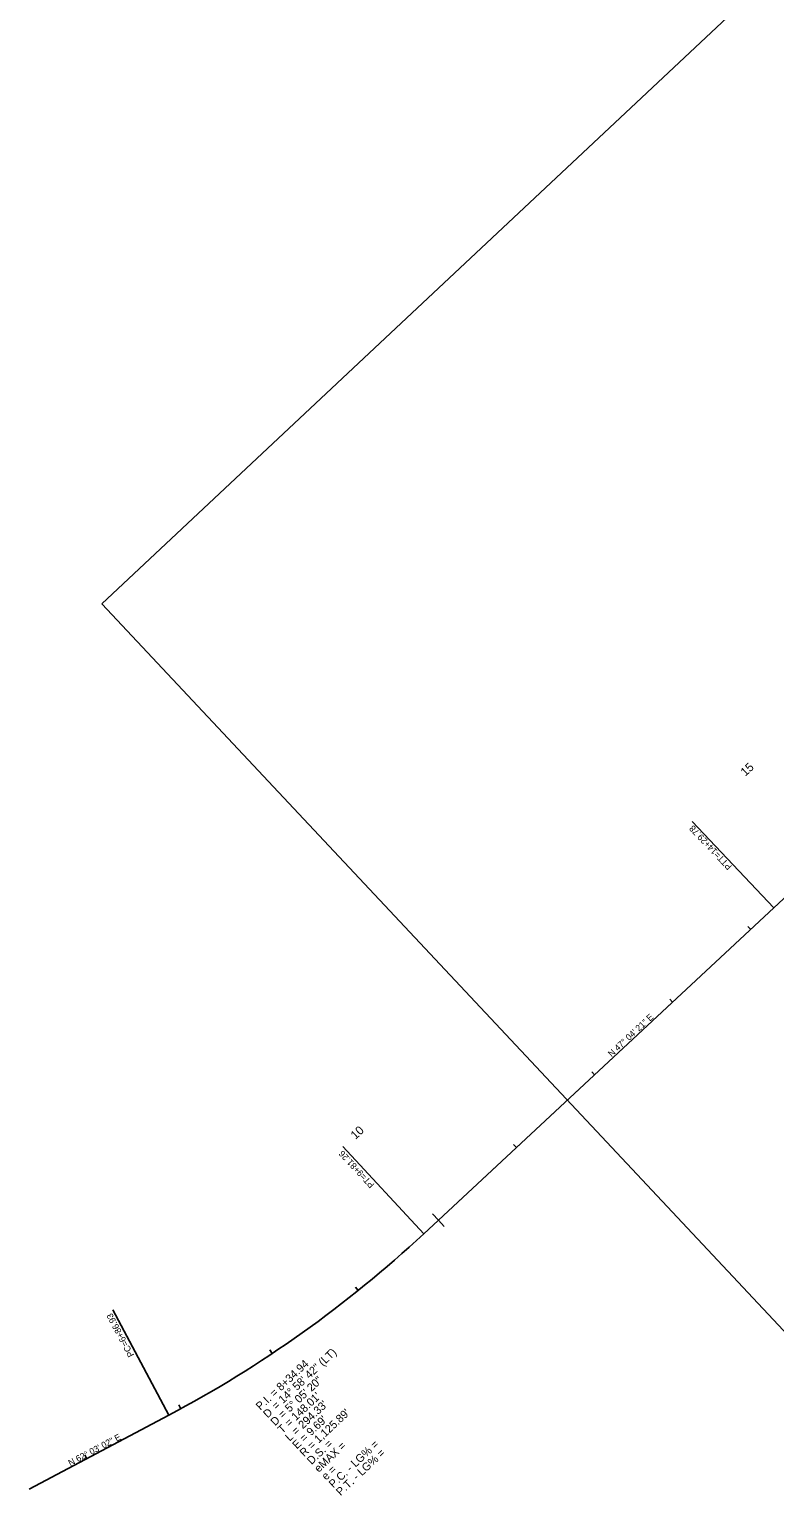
# Model space of a CAD drawing. Extents: x 1623239 to 1625698, y 1118659 to 1120751.
# Drawn here: x 1623239 to 1623938, y 1118659 to 1120033 of the extents above; entities that cross this region are included whole.
import ezdxf

# ---------------------------------------------------------------- set-up
doc = ezdxf.new("R2010")
doc.units = 0
for name, color, linetype in [('RD_HC_Cl', 7, 'Continuous'), ('RD_HC_Data', 7, 'Continuous'), ('RD_HC_Data_Tic', 7, 'Continuous'), ('RD_HC_TX_Sta50', 7, 'Continuous'), ('RD_SHT_ShtClip', 7, 'Continuous')]:
    doc.layers.add(name, color=color, linetype=linetype)

msp = doc.modelspace()

# ---------------------------------------------------------------- linework, layer by layer
at = {"layer": 'RD_HC_Cl'}
for p, q in [((1623937.2, 1119209.8), (1624678.7, 1119905.1)), ((1623937.2, 1119209.8), (1624678.7, 1119905.1)), ((1623608.8, 1118904.3), (1623937.2, 1119209.8)), ((1623622.6, 1118917.1), (1623937.2, 1119209.8)), ((1623239, 1118664.8), (1623369.7, 1118734.1))]:
    msp.add_line(p, q, dxfattribs=at)
msp.add_arc((1622842, 1119728.7), 1125.9, 297.9494, 312.9276, dxfattribs=at)
at = {"layer": 'RD_HC_Data'}
for p, q in [((1623937.2, 1119209.8), (1623860.6, 1119290.8)), ((1623608.8, 1118904.3), (1623532.9, 1118986)), ((1623369.7, 1118734.1), (1623317.2, 1118833.1))]:
    msp.add_line(p, q, dxfattribs=at)
at = {"layer": 'RD_HC_Data_Tic'}
for p, q in [((1623915.4, 1119189.5), (1623912.7, 1119192.4)), ((1623842.2, 1119121.4), (1623839.5, 1119124.3)), ((1623769, 1119053.3), (1623766.3, 1119056.2)), ((1623695.8, 1118985.2), (1623693.1, 1118988.1)), ((1623622.6, 1118917.1), (1623617.1, 1118922.9)), ((1623622.6, 1118917.1), (1623628, 1118911.2)), ((1623547.4, 1118851.2), (1623544.9, 1118854.3)), ((1623466.8, 1118792.1), (1623464.5, 1118795.4)), ((1623381.2, 1118740.3), (1623379.3, 1118743.8)), ((1623292.9, 1118693.4), (1623291, 1118696.9))]:
    msp.add_line(p, q, dxfattribs=at)
at = {"layer": 'RD_SHT_ShtClip'}
msp.add_lwpolyline([(1623307.1, 1119494.9), (1624620.1, 1120726.2), (1625372.5, 1119923.9), (1624059.6, 1118692.6)], close=True, dxfattribs=at)

# ---------------------------------------------------------------- texts
at = {"layer": 'RD_HC_Data'}
for s, height, rotation, p in [('PTT=14+29.78', 6, 133.4099, (1623898.3, 1119248.9)), ('N 47%%d 04\' 21" E', 6, 42.9276, (1623785, 1119069.7)), ('PT=9+81.26', 6, 132.9276, (1623563.1, 1118950.6)), ('PC=6+86.93', 6, 117.9494, (1623337.5, 1118790.6)), ('P.I. = 8+34.94', 7.5, 43.1627, (1623455.7, 1118738.4)), ('    = 14%%d 58\' 42" (LT)', 7.5, 43.1627, (1623462.5, 1118731.1)), ('D = 5%%d 05\' 20"', 7.5, 43.1627, (1623469.4, 1118723.8)), ("T = 148.01'", 7.5, 43.1627, (1623476.2, 1118716.6)), ("L = 294.33'", 7.5, 43.1627, (1623483.1, 1118709.3)), ('D', 7.5, 43.1627, (1623462.5, 1118731.1)), ("E = 9.69'", 7.5, 43.1627, (1623489.9, 1118702)), ("R = 1,125.89'", 7.5, 43.1627, (1623496.7, 1118694.7)), ('N 62%%d 03\' 02" E', 6, 27.9494, (1623277.5, 1118686.3)), ('D.S. = ', 7.5, 43.1627, (1623503.6, 1118687.4)), ('eMAX = ', 7.5, 43.1627, (1623510.4, 1118680.1)), ('P.C. - LG% = ', 7.5, 43.1627, (1623524.1, 1118665.5)), ('P.T. - LG% = ', 7.5, 43.1627, (1623530.9, 1118658.2)), ('e = ', 7.5, 43.1627, (1623517.3, 1118672.8))]:
    msp.add_text(s, height=height, rotation=rotation, dxfattribs=at).set_placement(p)
at = {"layer": 'RD_HC_TX_Sta50'}
for s, rotation, p in [('15', 43.1627, (1623910.4, 1119332.7)), ('10', 42.9276, (1623544.8, 1118992.2))]:
    msp.add_text(s, height=8, rotation=rotation, dxfattribs=at).set_placement(p)

doc.saveas('drawing.dxf')
